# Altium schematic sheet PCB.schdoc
size 431 x 309 mm; Symbol: Sheet-Symbol_A4; Device: Sheet-Symbol_A4; Company: 嘉立创EDA; Version: V1.0; Page Size: A4; @Project Name: HeatingStage; @Page Count: 1; @Update Date: 2024-02-05; @Create Date: 2024-02-04; @Schematic Name: Schematic1; @Page No: 1; @Page Name: P1
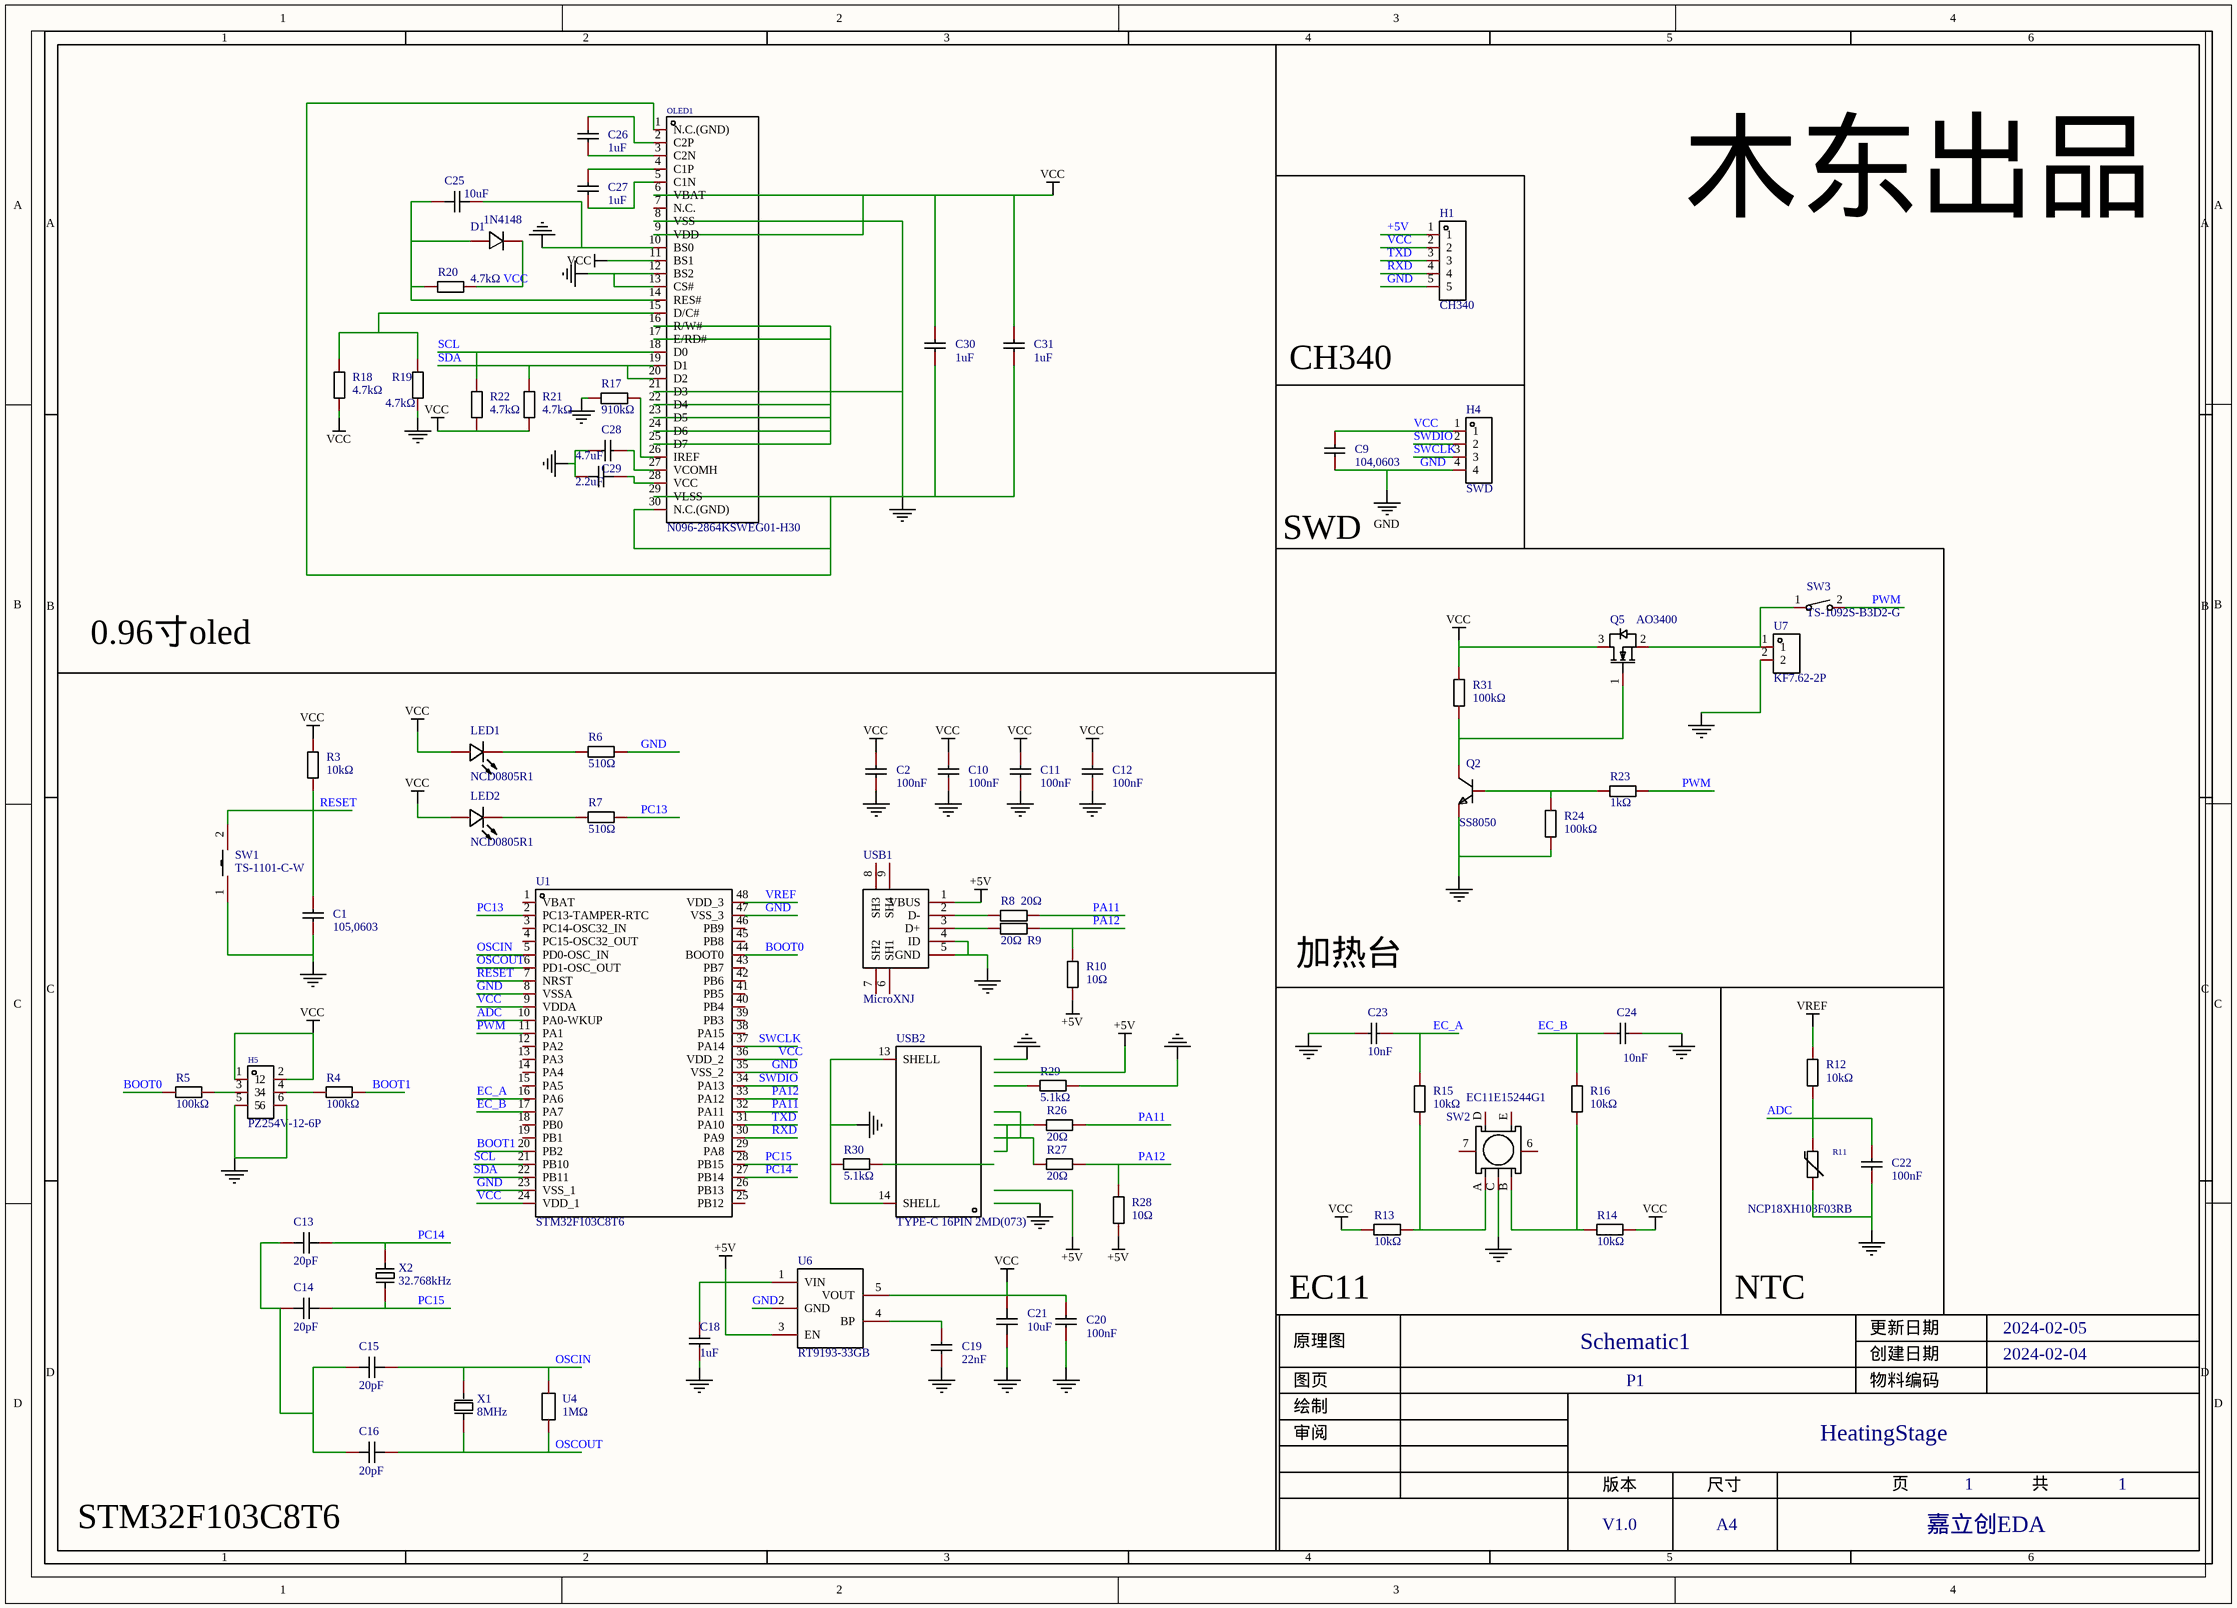
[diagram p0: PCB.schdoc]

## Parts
C1  105,0603  [C0603]
C2  100nF  [C0603]
C9  104,0603  [C0603]
C10  100nF  [C0603]
C11  100nF  [C0603]
C12  100nF  [C0603]
C13  20pF  [C0603]
C14  20pF  [C0603]
C15  20pF  [C0603]
C16  20pF  [C0603]
C18  1uF  [C0603]
C19  22nF  [C0603]
C20  100nF  [C0603]
C21  10uF  [C0603]
C22  100nF  [C0805]
C23  10nF  [C0805]
C24  10nF  [C0805]
C25  10uF  [C0805]
C26  1uF  [C0805]
C27  1uF  [C0805]
C28  4.7uF  [C0603]
C29  2.2uF  [C0805]
C30  1uF  [C0805]
C31  1uF  [C0805]
D1  1N4148  [DO-35_BD2.0-L4.2-P8.20-D0.5-RD]
H1  CH340  [HDR-TH_5P-P2.54-V-M]
H4  SWD  [HDR-TH_4P-P2.54-V-M]
H5  PZ254V-12-6P  [HDR-TH_6P-P2.54-V-M-R2-C3-S2.54]
LED1  NCD0805R1  [LED0805-R-RD]
LED2  NCD0805R1  [LED0805-R-RD]
OLED1  N096-2864KSWEG01-H30  [OLED_0.96-30P-P0.70-12864]
Q2  SS8050  [SOT-23-3_L2.9-W1.3-P1.90-LS2.4-BR]
Q5  AO3400  [SOT-23_L2.9-W1.3-P1.90-LS2.4-BR]
R3  10kΩ  [R0603]
R4  100kΩ  [R0603]
R5  100kΩ  [R0603]
R6  510Ω  [R0603]
R7  510Ω  [R0603]
R8  20Ω  [R1206]
R9  20Ω  [R1206]
R10  10Ω  [R0805_NEW]
R11  NCP18XH103F03RB  [R0603]
R12  10kΩ  [R0805]
R13  10kΩ  [R0805]
R14  10kΩ  [R0805]
R15  10kΩ  [R0805]
R16  10kΩ  [R0805]
R17  910kΩ  [R0603]
R18  4.7kΩ  [R0805]
R19  4.7kΩ  [R0805]
R20  4.7kΩ  [R0805]
R21  4.7kΩ  [R0805]
R22  4.7kΩ  [R0805]
R23  1kΩ  [R0805]
R24  100kΩ  [R0805]
R26  20Ω  [R1206]
R27  20Ω  [R1206]
R28  10Ω  [R0805_NEW]
R29  5.1kΩ  [R0805]
R30  5.1kΩ  [R0805]
R31  100kΩ  [R0805]
SW1  TS-1101-C-W  [SW-SMD_L6.0-W3.3-LS8.0]
SW2  EC11E15244G1  [SW-TH_EC11E15244G1]
SW3  TS-1092S-B3D2-G  [SW-SMD_L6.1-W3.6-LS7.9]
U1  STM32F103C8T6  [LQFP-48_L7.0-W7.0-P0.50-LS9.0-BL]
U4  1MΩ  [R0603]
U6  RT9193-33GB  [SOT-23-5_L3.0-W1.7-P0.95-LS2.8-BL]
U7  KF7.62-2P  [CONN-TH_KF7.62-2P]
USB1  MicroXNJ  [MICRO-USB-SMD_MICROXNJ]
USB2  TYPE-C 16PIN 2MD(073)  [USB-C-SMD_TYPE-C-6PIN-2MD-073]
X1  8MHz  [OSC-TH_L10.0-W4.5-P5.00]
X2  32.768kHz  [OSC-SMD_L3.2-W1.5]

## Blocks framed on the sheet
0.96寸oled: C25-C31 D1 OLED1 R17-R22
CH340: H1
STM32F103C8T6: C1 C2 C10-C16 C18-C21 H5 LED1 LED2 R3-R10 R26-R30 SW1 U1 U4 U6 USB1 USB2 X1 X2
NTC: C22 R11 R12

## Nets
+5V: C18.2 H1.1 R10.1 R28.1 U6.1(VIN) U6.3(EN) USB1.1(VBUS)
GND: C9.2 H1.5 H4.4 R6.2 U1.8(VSSA) U1.23(VSS_1) U1.35(VSS_2) U1.47(VSS_3) U6.2(GND)
NetC1_1: C1.1 C2.1 C10.1 C11.1 C12.1 C18.1 C19.1 C20.1 C21.1 C22.1 C23.1 C24.2 C25.2 C28.1 C29.2 C30.1 C31.1 H5.5 H5.6 OLED1.1(N.C.(GND)) OLED1.8(VSS) OLED1.10(BS0) OLED1.12(BS2) OLED1.13(CS#) OLED1.16(R/W#) OLED1.17(E/RD#) OLED1.21(D3) OLED1.22(D4) OLED1.23(D5) OLED1.24(D6) OLED1.25(D7) OLED1.29(VLSS) OLED1.30(N.C.(GND)) Q2.2(E) R11.2 R17.1 R19.1 R24.1 R29.2 R30.1 SW1.1 SW2.C U7.2 USB1.4(ID) USB1.5(GND) USB2.13(SHELL) USB2.14(SHELL)
VCC: C2.2 C9.1 C10.2 C11.2 C12.2 C20.2 C21.2 C30.2 C31.2 D1.1(C) H1.2 H4.1 H5.1 H5.2 LED1.1(+) LED2.1(+) OLED1.6(VBAT) OLED1.9(VDD) OLED1.11(BS1) Q5.3(D) R3.2 R13.1 R14.2 R18.1 R20.2 R21.1 R22.1 R31.2 U1.9(VDDA) U1.24(VDD_1) U1.36(VDD_2) U6.5(VOUT)
VREF: R12.2 U1.48(VDD_3)
ADC: C22.2 R11.1 R12.1 U1.10(PA0-WKUP)
BOOT0: R5.1 U1.44(BOOT0)
BOOT1: R4.2 U1.20(PB2)
EC_A: C23.2 R15.2 U1.16(PA6)
EC_B: C24.1 R16.2 U1.17(PA7)
OSCIN: C15.2 U1.5(PD0-OSC_IN) U4.2 X1.1(OSC1)
OSCOUT: C16.2 U1.6(PD1-OSC_OUT) U4.1 X1.2(OSC2)
PA11: R8.2 R26.2 U1.32(PA11)
PA12: R9.2 R10.2 R27.2 R28.2 U1.33(PA12)
PC13: R7.2 U1.2(PC13-TAMPER-RTC)
PC14: C13.1 U1.27(PB14) X2.2
PC15: C14.1 U1.28(PB15) X2.1
PWM: R23.2 SW3.2 U1.11(PA1)
RESET: C1.2 R3.1 SW1.2 U1.7(NRST)
RXD: H1.4 U1.30(PA9)
SCL: OLED1.18(D0) R22.2 U1.21(PB10)
SDA: OLED1.19(D1) OLED1.20(D2) R21.2 U1.22(PB11)
SWCLK: H4.3 U1.37(PA14)
SWDIO: H4.2 U1.34(PA13)
TXD: H1.3 U1.31(PA10)
NetC13_2: C13.2 C14.2 C15.1 C16.1
NetC19_2: C19.2 U6.4(BP)
NetC25_1: C25.1 D1.2(A) OLED1.14(RES#) R20.1
NetC26_1: C26.1 OLED1.3(C2N)
NetC26_2: C26.2 OLED1.2(C2P)
NetC27_1: C27.1 OLED1.5(C1N)
NetC27_2: C27.2 OLED1.4(C1P)
NetC28_2: C28.2 OLED1.27(VCOMH)
NetC29_1: C29.1 OLED1.28(VCC)
NetH5_3: H5.3 R5.2
NetH5_4: H5.4 R4.1
NetLED1_2: LED1.2(-) R6.1
NetLED2_2: LED2.2(-) R7.1
NetOLED1_15: OLED1.15(D/C#) R18.2 R19.2
NetOLED1_26: OLED1.26(IREF) R17.2
NetQ2_1: Q2.1(B) R23.1 R24.2
NetQ2_3: Q2.3(C) Q5.1(G) R31.1
NetQ5_2: Q5.2(S) SW3.1 U7.1
NetR8_1: R8.1 USB1.2(D-)
NetR9_1: R9.1 USB1.3(D+)
NetR13_2: R13.2 R15.1 SW2.A
NetR14_1: R14.1 R16.1 SW2.B

Not connected (* = marked no-connect by the designer): OLED1 7(N.C.); R26 1; R27 1; R29 1; R30 2; SW2 6 7 D E; U1 1(VBAT) 3(PC14-OSC32_IN) 4(PC15-OSC32_OUT) 12(PA2) 13(PA3) 14(PA4) 15(PA5) 18(PB0) 19(PB1) 25(PB12) 26(PB13) 29(PA8) 38(PA15) 39(PB3) 40(PB4) 41(PB5) 42(PB6) 43(PB7) 45(PB8) 46(PB9); USB1 6(SH1) 7(SH2) 8(SH3) 9(SH4); USB2 1(GND) 2(VBUS) 3(SBU2) 4(CC1) 5(DN2) 6(DP1) 7(DN1) 8(DP2) 9(SBU1) 10(CC2) 11(VBUS) 12(GND)

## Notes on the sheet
- 木东出品
- SWD
- 加热台
- (near R13) EC11

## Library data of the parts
C1 C2 C9-C12 C20 = 0603B104K500NT: Manufacturer: FH(风华); Add into BOM: yes; Tolerance: ±10%; Voltage Rated: 50V; Temperature Coefficient: X7R; Description: 容值:100nF;精度:±10%;额定电压:50V;材质(温度系数):X7R;
C13-C16 = 0603CG200J500NT: Manufacturer: FH(风华); Add into BOM: yes; Tolerance: ±5%; Voltage Rated: 50V; Temperature Coefficient: C0G; Description: 容值:20pF;精度:±5%;额定电压:50V;材质(温度系数):C0G;
C18 = CL10A105KB8NNNC: Manufacturer: SAMSUNG(三星); Add into BOM: yes; Tolerance: ±10%; Voltage Rated: 50V; Temperature Coefficient: X5R; Description: 容值:1uF;精度:±10%;额定电压:50V;材质(温度系数):X5R;
C19 = 0603B223K500NT: Manufacturer: FH(风华); Add into BOM: yes; Tolerance: ±10%; Voltage Rated: 50V; Temperature Coefficient: X7R; Description: 容值:22nF;精度:±10%;额定电压:50V;材质(温度系数):X7R;
C21 = CL10A106KP8NNNC: Manufacturer: SAMSUNG(三星); Add into BOM: yes; Tolerance: ±10%; Voltage Rated: 10V; Temperature Coefficient: X5R; Description: 容值:10uF;精度:±10%;额定电压:10V;材质(温度系数):X5R;
C22 = 0805B104K500NT: Manufacturer: FH(风华); Add into BOM: yes; Tolerance: ±10%; Voltage Rated: 50V; Temperature Coefficient: X7R; Description: 容值:100nF;精度:±10%;额定电压:50V;材质(温度系数):X7R;
C23 C24 = 0805B103K500NT_C52278: Manufacturer: FH(风华); Add into BOM: yes; Tolerance: ±10%; Voltage Rated: 50V; Temperature Coefficient: X7R; Description: 容值:10nF;精度:±10%;额定电压:50V;材质(温度系数):X7R;
C25 = GRM21BR61H106KE43L: Manufacturer: muRata(村田); Add into BOM: yes; Tolerance: ±10%; Voltage Rated: 50V; Temperature Coefficient: X5R; Description: 容值:10uF;精度:±10%;额定电压:50V;材质(温度系数):X5R;
C26 C27 C30 C31 = CL21B105KBFNNNE: Manufacturer: SAMSUNG(三星); Add into BOM: yes; Tolerance: ±10%; Voltage Rated: 50V; Temperature Coefficient: X7R; Description: 容值:1uF;精度:±10%;额定电压:50V;材质(温度系数):X7R;
C28 = CL10A475KO8NNNC: Manufacturer: SAMSUNG(三星); Add into BOM: yes; Tolerance: ±10%; Voltage Rated: 16V; Temperature Coefficient: X5R; Description: 容值:4.7uF;精度:±10%;额定电压:16V;材质(温度系数):X5R;
C29 = CL21A225KBQNNNE: Manufacturer: SAMSUNG(三星); Add into BOM: yes; Tolerance: ±10%; Voltage Rated: 50V; Temperature Coefficient: X5R; Description: 容值:2.2uF;精度:±10%;额定电压:50V;材质(温度系数):X5R;
D1 = 1N4148_C402212: Manufacturer: LGE(鲁光); Add into BOM: yes; Forward Voltage (Vf@If): 1V@10mA; Reverse Voltage (Vr): 75V; Average Rectified Current (Io): 150mA; Power Dissipation: 500mW; Reverse Leakage Current: 5uA@75V; Reverse Recovery Time (trr): 4ns; Description: 二极管配置:-;正向压降(Vf):1V@10mA;直流反向耐压(Vr):75V;平均整流电流(Io):150mA;功率:500mW;反向恢复时间(trr):4ns;
H1 = PZ254V-11-05P: Manufacturer: XFCN(兴飞); Add into BOM: yes; Pin Structure: 1x5P; Pitch: 2.54mm; Circluar Pins/Square Pins: 方针; Description: 插针结构:1x5P;间距:2.54mm;行距:-;圆针/方针:方针;安装类型:直插;排数:单排;总PIN位数:5P;额定电流:-;额定电压:-;配合针长度:6mm;塑高:2.5mm;端接针长度:3mm;触头材质:黄铜;触头镀层:-;工作温度范围:-40℃~+105℃;颜色:黑色;
H4 = PZ254V-11-04P: Manufacturer: XFCN(兴飞); Symbol: PZ254V-11-04P_C2691448; Add into BOM: yes; Pin Structure: 1x4P; Pitch: 2.54mm; Circluar Pins/Square Pins: 方针; Current Rating (Max): 3A; Voltage Rating (Max): 250V; Description: 插针结构:1x4P;间距:2.54mm;行距:-;圆针/方针:方针;安装类型:直插;排数:单排;总PIN位数:4P;额定电流:3A;额定电压:250V;配合针长度:6mm;塑高:2.5mm;端接针长度:3mm;触头材质:-;工作温度范围:-40℃~+105℃;颜色:黑色;
H5 = PZ254V-12-6P: Manufacturer: XFCN(兴飞); Add into BOM: yes; Pin Structure: 2x3P; Pitch: 2.54mm; Circluar Pins/Square Pins: 方针; Description: 插针结构:2x3P;间距:2.54mm;行距:2.54mm;圆针/方针:方针;安装类型:直插;排数:双排;总PIN位数:6P;额定电流:-;额定电压:-;配合针长度:6mm;塑高:2.5mm;端接针长度:3mm;触头材质:黄铜;触头镀层:-;工作温度范围:-40℃~+105℃;颜色:黑色;
LED1 LED2 = NCD0805R1: Manufacturer: 国星光电; Symbol: FC-2012HRK-620D; Add into BOM: yes; Emitted Color: 红色; Forward Voltage (VF): 1.6V~2.6V; Power Dissipation: 65mW; Forward Current: 20mA; Dominant Wavelength: 615nm~630nm; Diode Configuration: 独立二极管; Lens Color: 无色透明透镜; Luminous Intensity: 67mcd~195mcd; Viewing Angle: 130°; Description: 灯头类型:-;发光颜色:红色;正向电压(VF):1.6V~2.6V;功率:65mW;正向电流:20mA;主波长:615nm~630nm;二极管配置:独立二极管;透镜颜色:无色透明透镜;色温:-;发光强度:67mcd~195mcd;发光角度:130°;载带方式:-;工作温度:-30℃~+85℃;
OLED1 = N096-2864KSWEG01-H30: Manufacturer: Newvision(新智景); Add into BOM: yes; Main Control Chip: SSD1306; Description: 主控芯片:SSD1306;尺寸(inch):0.96;
Q2 = SS8050_C2150: Manufacturer: CJ(江苏长电/长晶); Add into BOM: yes; Transistor Type: NPN; Collector Current (Ic): 1.5A; Collector-Emitter Breakdown Voltage (Vceo): 25V; Power Dissipation (Pd): 300mW; DC Current Gain (hFE@Ic,Vce): 200@100mA,1V; Transition Frequency (fT): 100MHz; Collector Cut-Off Current (Icbo): 100nA; Collector-Emitter Saturation Voltage (VCE(sat)@Ic,Ib): 500mV@800mA,80mA; Description: 晶体管类型:NPN;集电极电流(Ic):1.5A;集射极击穿电压(Vceo):25V;功率(Pd):300mW;直流电流增益(hFE@Ic,Vce):200@100mA,1V;
Q5 = AO3400_C2938367: Manufacturer: GOODWORK(固得沃克); Add into BOM: yes; Type: N沟道; Drain Source Voltage (Vdss): 30V; Continuous Drain Current (Id): 5.8A; Power Dissipation (Pd): 1.5W; Drain Source On Resistance (RDS(on)@Vgs,Id): 35mΩ@10V,5.8A; Gate Threshold Voltage (Vgs(th)@Id): 1.2V@250uA; Input Capacitance (Ciss@Vds): 1.05nF@15V; Reverse Transfer Capacitance (Crss@Vds): 77pF@15V; Description: 类型:N沟道;漏源电压(Vdss):30V;连续漏极电流(Id):5.8A;功率(Pd):1.5W;导通电阻(RDS(on)@Vgs,Id):35mΩ@10V,5.8A;阈值电压(Vgs(th)@Id):1.2V@250uA;
R3 = 0603WAF1002T5E: Manufacturer: UNI-ROYAL(厚声); Add into BOM: yes; Tolerance: ±1%; Power(Watts): 100mW; Overload Voltage (Max): 75V; Temperature Coefficient: ±100ppm/℃; Description: 电阻类型:厚膜电阻;阻值:10kΩ;精度:±1%;功率:100mW;最大工作电压:75V;温度系数:±100ppm/℃;
R4 R5 = RC0603FR-07100KL: Manufacturer: YAGEO(国巨); Add into BOM: yes; Tolerance: ±1%; Power(Watts): 100mW; Overload Voltage (Max): 75V; Temperature Coefficient: ±100ppm/℃; Description: 电阻类型:厚膜电阻;阻值:100kΩ;精度:±1%;功率:100mW;最大工作电压:75V;温度系数:±100ppm/℃;
R6 R7 = 0603WAF5100T5E: Manufacturer: UNI-ROYAL(厚声); Add into BOM: yes; Tolerance: ±1%; Power(Watts): 100mW; Overload Voltage (Max): 75V; Temperature Coefficient: ±100ppm/℃; Description: 电阻类型:厚膜电阻;阻值:510Ω;精度:±1%;功率:100mW;最大工作电压:75V;温度系数:±100ppm/℃;
R8 R9 R26 R27 = 1206W4F200JT5E: Manufacturer: UNI-ROYAL(厚声); Add into BOM: yes; Tolerance: ±1%; Power(Watts): 250mW; Overload Voltage (Max): 200V; Temperature Coefficient: ±100ppm/℃; Description: 电阻类型:厚膜电阻;阻值:20Ω;精度:±1%;功率:250mW;最大工作电压:200V;温度系数:±100ppm/℃;
R10 R28 = 0805W8F100JT5E: Manufacturer: UNI-ROYAL(厚声); Add into BOM: yes; Tolerance: ±1%; Power(Watts): 125mW; Overload Voltage (Max): 150V; Temperature Coefficient: ±200ppm/℃; Description: 电阻类型:厚膜电阻;阻值:10Ω;精度:±1%;功率:125mW;最大工作电压:150V;温度系数:±200ppm/℃;
R11 = NCP18XH103F03RB: Manufacturer: muRata(村田); Value: 10KΩ(1002); Add into BOM: yes; Resistance @ 25℃: 10kΩ; B Constant (25℃/50℃): 3380K; Resistance Tolerance: ±1%; B Constant (25℃/85℃): 3434K; B Constant (25℃/100℃): 3455K; Power: 100mW; Steady State Current (Max): 310uA; Description: 阻值(25℃):10kΩ;B值(25℃/50℃):3380K;电阻精度:±1%;功率:100mW;B值精度:±1%;最大稳态电流(25℃):310uA;
R12-R16 = 0805W8F1002T5E_C17414: Manufacturer: UNI-ROYAL(厚声); Add into BOM: yes; Tolerance: ±1%; Power(Watts): 125mW; Overload Voltage (Max): 150V; Temperature Coefficient: ±100ppm/℃; Description: 电阻类型:厚膜电阻;阻值:10kΩ;精度:±1%;功率:125mW;最大工作电压:150V;温度系数:±100ppm/℃;
R17 = 0603WAF9103T5E: Manufacturer: UNI-ROYAL(厚声); Add into BOM: yes; Tolerance: ±1%; Power(Watts): 100mW; Overload Voltage (Max): 75V; Temperature Coefficient: ±100ppm/℃; Description: 电阻类型:厚膜电阻;阻值:910kΩ;精度:±1%;功率:100mW;最大工作电压:75V;温度系数:±100ppm/℃;
R18-R22 = 0805W8F4701T5E: Manufacturer: UNI-ROYAL(厚声); Add into BOM: yes; Tolerance: ±1%; Power(Watts): 125mW; Overload Voltage (Max): 150V; Temperature Coefficient: ±100ppm/℃; Description: 电阻类型:厚膜电阻;阻值:4.7kΩ;精度:±1%;功率:125mW;最大工作电压:150V;温度系数:±100ppm/℃;
R23 = 0805W8F1001T5E: Manufacturer: UNI-ROYAL(厚声); Add into BOM: yes; Tolerance: ±1%; Power(Watts): 125mW; Overload Voltage (Max): 150V; Temperature Coefficient: ±100ppm/℃; Description: 电阻类型:厚膜电阻;阻值:1kΩ;精度:±1%;功率:125mW;最大工作电压:150V;温度系数:±100ppm/℃;
R24 R31 = 0805W8F1003T5E: Manufacturer: UNI-ROYAL(厚声); Symbol: 0805W8F1003T5E_C149504; Add into BOM: yes; Tolerance: ±1%; Power(Watts): 125mW; Overload Voltage (Max): 150V; Temperature Coefficient: ±100ppm/℃; Description: 电阻类型:厚膜电阻;阻值:100kΩ;精度:±1%;功率:125mW;最大工作电压:150V;温度系数:±100ppm/℃;
R29 R30 = 0805W8F5101T5E: Manufacturer: UNI-ROYAL(厚声); Add into BOM: yes; Tolerance: ±1%; Power(Watts): 125mW; Overload Voltage (Max): 150V; Temperature Coefficient: ±100ppm/℃; Description: 电阻类型:厚膜电阻;阻值:5.1kΩ;精度:±1%;功率:125mW;最大工作电压:150V;温度系数:±100ppm/℃;
SW1 = TS-1101-C-W: Manufacturer: XKB Connectivity(中国星坤); Add into BOM: yes; Circuit: 单刀单掷; Actuator Style: 矩形按钮; Operating Force: 260gf; Switch Length: 6mm; Switch Width: 3.6mm; Switch Height: 2.5mm; Strike Gundam: 不带; Contact Current: 50mA; Voltage Rating (DC): 12V; Actuator/Cap Color: 白色带淡绿; With Lamp: 无; Mechanical Life: 5万次; Description: 电路结构:单刀单掷;按钮形状:矩形按钮;作用力:260gf;安装方式:立贴;开关长度:6mm;开关宽度:3.6mm;开关高度:2.5mm;带支架:不带;触点电流:50mA;额定电压(AC):-;额定电压(DC):12V;额定功率:-;绝缘电阻:-;带灯:无;机械寿命:5万次;
SW2 = EC11E15244G1: Manufacturer: ALPSALPINE(阿尔卑斯阿尔派); Add into BOM: yes
SW3 = TS-1092S-B3D2-G: Manufacturer: Yuandi(元迪); Add into BOM: yes; Circuit: 单刀单掷; Actuator Style: 矩形按钮; Operating Force: 250gf; Switch Length: 6.1mm; Switch Width: 3.6mm; Switch Height: 2.5mm; Strike Gundam: 不带; Actuator/Cap Color: 灰色; Pin Style: 鸥翼型; Description: 电路结构:单刀单掷;按钮形状:矩形按钮;作用力:250gf;安装方式:立贴;开关长度:6.1mm;开关宽度:3.6mm;开关高度:2.5mm;带支架:不带;机械寿命:-;
U1 = STM32F103C8T6: Manufacturer: ST(意法半导体); Add into BOM: yes; CPU Core: CM3; Program Storage Size: 64KB; RAM Size: 20KB; GPIO Ports Number: 37; Operating Voltage Range: 2V~3.6V; CPU Maximum Speed: 72MHz; Program Memory Type: FLASH; ADC (Bit): 12bit; Universal Serial Bus: 有; Peripheral/Function: 看门狗；DMA；看门狗；片载温度传感器; Description: CPU内核:CM3;程序存储容量:64KB;RAM总容量:20KB;GPIO端口数量:37;工作电压范围:2V~3.6V;CPU最大主频:72MHz;程序存储器类型:FLASH;
U4 = SC0603F1004F2BNRH: Manufacturer: Sunway(信维通信); Add into BOM: yes; Tolerance: ±1%; Temperature Coefficient: ±100ppm/℃; Description: 阻值:1MΩ;精度:±1%;功率:-;温度系数:±100ppm/℃;
U6 = RT9193-33GB: Manufacturer: RICHTEK(立锜); Add into BOM: yes; Output Type: 固定; Maximum Input Voltage: 5.5V; Output Voltage: 3.3V; MAX Output Current: 300mA; Power Supply Rejection Ratio (PSRR): 70dB; Dropout Voltage: 300mV@(300mA); standby current: 130uA; Output Polarity: 正极; Number of Outputs: 1; Description: 输出类型:固定;最大输入电压:5.5V;输出电压:3.3V;最大输出电流:300mA;电源纹波抑制比(PSRR):70dB;输出极性:正极;
U7 = KF7.62-2P: Manufacturer: KEFA(科发); Add into BOM: yes; Barrier Type: 两面; Pitch: 7.62mm; Structure: 1x2P; Pin Location: 边脚; Current Rating (Max): 24A; Voltage Rating (Max): 450V; Wire Gauge - AWG: 12~22; Wire Gauge - mm2: 2.5; Number of PINs Per Row: 2; Description: 隔板类型:两面;间距:7.62mm;结构:1x2P;安装方式:直针;引脚位置:边脚;排数:1;额定电流:24A;额定电压:450V;线规 - AWG:12~22;线规 - 平方毫米:2.5;工作温度范围:-40℃~+105℃;颜色:黑色;每排PIN数:2;
USB1 = MicroXNJ: Manufacturer: SHOU HAN(首韩); Add into BOM: yes; Connector Type: Micro-B; Gender: 母; Number of Ports: 1; Number of Contacts: 5P; Current Rating - Power (Max): 1A; Description: 连接器类型:Micro-B;标准:USB 2.0;公母:母;端口数量:1;触点数量:5P;安装方式:卧贴;额定电流 - 电源:1A;工作温度范围:-20℃~+85℃;
USB2 = TYPE-C 16PIN 2MD(073): Manufacturer: SHOU HAN(首韩); Add into BOM: yes; Gender: 母; Number of Ports: 1; Number of Contacts: 16P; Current Rating - Power (Max): 5A; Description: 连接器类型:Type-C;标准:-;公母:母;端口数量:1;触点数量:16P;安装方式:卧贴;额定电流 - 电源:5A;工作温度范围:-25℃~+85℃;
X1 = X49SD8MSD2SC: Manufacturer: YXC(扬兴晶振); Add into BOM: yes; Crystal Type: 直插晶振; Normal temperature Frequency Tolerance: ±20ppm; External load capacitor: 20pF; Frequency Stability(Full temperature range): ±30ppm; Description: 晶振类型:直插晶振;频率:8MHz;常温频差:±20ppm;外接负载电容:20pF;频率稳定度(全温):±30ppm;
X2 = X321532768KGD2SI: Manufacturer: YXC(扬兴晶振); Add into BOM: yes; Crystal Type: 贴片晶振; Normal temperature Frequency Tolerance: ±20ppm; External load capacitor: 12.5pF; Description: 晶振类型:贴片晶振;频率:32.768kHz;常温频差:±20ppm;外接负载电容:12.5pF;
